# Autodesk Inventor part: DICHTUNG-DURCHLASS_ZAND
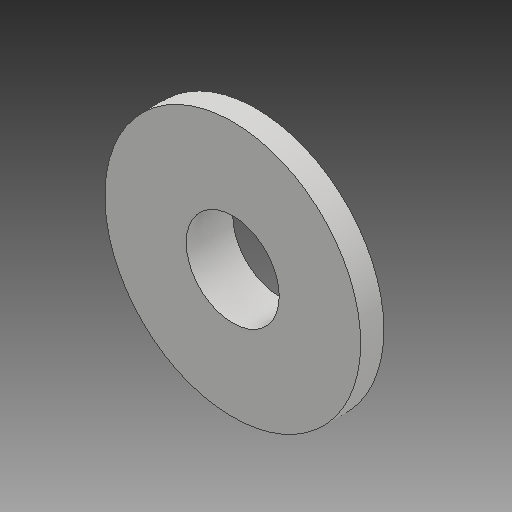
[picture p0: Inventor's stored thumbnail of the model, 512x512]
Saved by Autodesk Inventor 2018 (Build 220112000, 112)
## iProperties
Created: 2019-01
Part Number: DICHTUNG-DURCHLASS_ZAND
Material: Generisch
Document SubType Name: Modeling
Designer: zand
Density: 1 g/cm^3
Appearance: Vorgabe
Author: zand
Revision Number: 1LAST_VERSION
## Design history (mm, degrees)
feature "Basis1"
node "Volumenkörper1"
